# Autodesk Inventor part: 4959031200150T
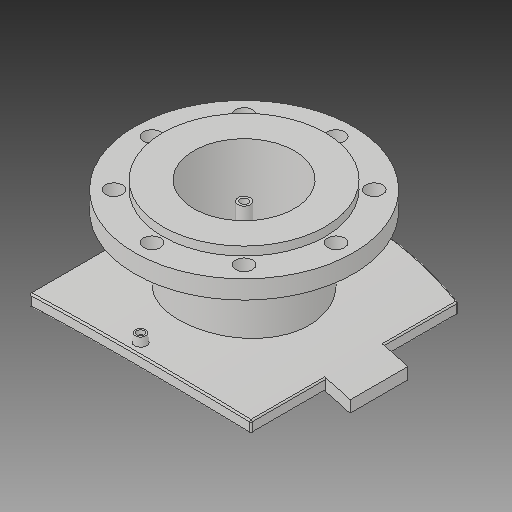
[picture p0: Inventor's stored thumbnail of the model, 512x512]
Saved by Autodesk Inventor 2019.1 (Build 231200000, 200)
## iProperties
Created: 2017-10
Part Number: 4959031200150T
Material: Generic
Description: PLASSON FLANGED BRANCH SADDLE 1200x150
Document SubType Name: Modeling
Designer: KIM
Mass: 2339.99 g
Surface Area: 3251.55 cm^2
Volume: 2339.99 cm^3
Density: 1 g/cm^3
Appearance: Default
Author: KIM
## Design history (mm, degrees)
derived "495904_495903.ipt"
feature "Solid1::495904_495903.ipt"
feature "Solid2::495904_495903.ipt"
tag "TaggingFeature1"
body "Solid1"
other parameters: "d1" = 15, "d2" = 288, "d4" = 0, "d6" = 75, "d7" = 0, "d12" = 625.6, "d13" = 14, "d14" = 135, "d16" = 5 deg, "d18" = 4, "d19" = 14, "d20" = 0, "d21" = 3, "d22" = 0, "d23" = 746, "d36" = 135, "d38" = 0, "d39" = 2, "d41" = 131, "d42" = 212, "d43" = 285, "d44" = 104.8, "d46" = 169.6, "d47" = 16, "d48" = 10.4, "d49" = 91.7, "d51" = 1224, "d53" = 0, "d54" = 22, "d57" = 0, "d59" = 360 deg, "d61" = 24, "d63" = 0, "d66" = 131, "d67" = 15, "d68" = 65.5, "d70" = 0, "d71" = 2, "d_1" = 212, "H_" = 131, "x_" = 15, "D_" = 16, "DN_" = 131, "D_1" = 285, "t_" = 24, "s_" = 22
